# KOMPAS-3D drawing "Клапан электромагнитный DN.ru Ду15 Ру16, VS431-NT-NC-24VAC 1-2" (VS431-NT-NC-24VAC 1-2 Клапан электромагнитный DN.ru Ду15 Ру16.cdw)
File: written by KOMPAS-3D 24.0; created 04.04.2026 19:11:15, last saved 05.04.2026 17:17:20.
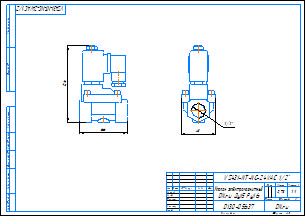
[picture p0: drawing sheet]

Document properties: c3d_UniqueCompID: ef56311e-7521-43dc-8291-0e6108b3d81d; Обозначение: VS400-ET-NC-220VAC 1-2; Наименование: Клапан электромагнитный DN.ru Ду15 Ру16; Автор: artio; Класс точности: c; Знак неуказанной шероховатости: Шероховатость не задана; Рассекать на разрезах: Да; c3d_UniqueCompID: ef56311e-7521-43dc-8291-0e6108b3d81d; Обозначение: VS400-ET-NC-220VAC 3-8; Наименование: Клапан электромагнитный DN.ru Ду10 Ру16; Автор: artio; Класс точности: c; Знак неуказанной шероховатости: Шероховатость не задана; Рассекать на разрезах: Да; Автор: artio; Форматы листов документа: A3; Полное имя файла: VS431-NT-NC-24VAC 1-2 Клапан электромагнитный DN.ru Ду15 Ру16.m3d; Масса: 0.732; Наименование: Клапан электромагнитный DN.ru Ду15 Ру16; Количество листов документа: 1; Примечание: D130-05631

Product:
- Body: Тело 1  | qty 1
    Масса: 1.030062
- Part/product: Клапан электромагнитный DN.ru Ду15 Ру16  | designation VS431-NT-NC-24VAC 1-2
    Масса: 0.732
    Раздел спецификации: Прочие изделия
    Форматы листов документа: A3
    Примечание: D130-05631
    additional columns: ef56311e-7521-43dc-8291-0e6108b3d81d; VS400-ET-NC-220VAC 1-2; artio; c; Шероховатость не задана; Да

Views: Вид 1, Спереди, Проекционный вид 2
Referenced files in C:\Users\artio\OneDrive\Рабочий стол\Клапан электромагнитный DN.ru\VS400-ET-NC\VS400-ET-NC-24VDC\: VS400-ET-NC-24VDC 3-8 Клапан электромагнитный DN.ru Ду10 Ру16.m3d
Referenced files in C:\Users\artio\OneDrive\Рабочий стол\Клапан электромагнитный DN.ru\VS431\VS431-NT-NC\VS431-NT-NC-24VAC\Ду15\: VS431-NT-NC-24VAC 1-2 Клапан электромагнитный DN.ru Ду15 Ру16.m3d
Referenced files in C:\Users\artio\OneDrive\Рабочий стол\Клапан электромагнитный DN.ru\VS400-ET-NC\: VS400-ET-NC-24VDC 3-8 Клапан электромагнитный DN.ru Ду10 Ру16.cdw
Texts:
  VS431-NT-NC-24VAC 1-2
  Клапан электромагнитный
  DN.ru Ду15 Ру16
  VS431-NT-NC-24VAC 1/2"
  VS431-NT-NC-24VAC 1/2"-
  Клапан электромагнитный DN.ru Ду15 Ру16
  VS431-NT-NC-24VAC 1-2 Клапан электромагнитный DN.ru Ду15 Ру16
Dimensions and other numbers on the sheet: 0; 3; 2; 4; 48; 1/2"; 66; 106; 1:1; 1; 0,73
